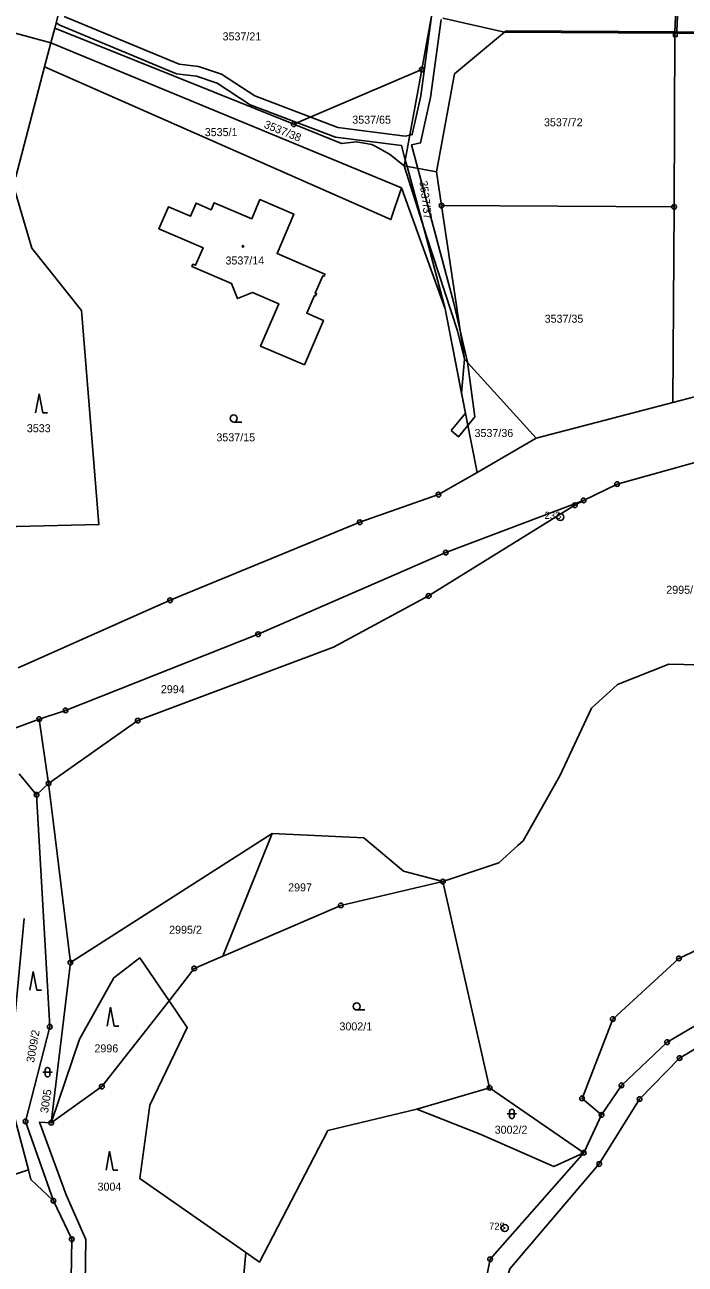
# Model space of a CAD drawing. Extents: x -644096 to -634268, y -1141430 to -1133463.
# Drawn here: x -641189.8 to -641049.4, y -1138498.2 to -1138235 of the extents above; entities that cross this region are included whole.
import ezdxf

# ---------------------------------------------------------------- set-up
doc = ezdxf.new("R2010")
doc.units = 0
for name, color, linetype in [('_CIVIL_CONSTRUCTION', 7, 'Continuous'), ('B_Hranice _3D', 7, 'Continuous'), ('M_Svah_Zarez', 7, 'Continuous'), ('svrsek_osa_sjezdy', 7, 'Continuous'), ('svrsek_osa_VRT', 7, 'Continuous'), ('terminal_VRT', 7, 'Continuous')]:
    doc.layers.add(name, color=color, linetype=linetype)

msp = doc.modelspace()

# ---------------------------------------------------------------- linework, layer by layer
at = {"layer": '_CIVIL_CONSTRUCTION'}
for centre, radius in [((-641105.4, -1138244.5), 0.5), ((-641105.4, -1138244.5), 0.0303), ((-641132.62, -1138256.11), 0.5), ((-641132.62, -1138256.11), 0.0303), ((-641101.19, -1138273.38), 0.5), ((-641101.19, -1138273.38), 0.0303), ((-641051.82, -1138273.67), 0.5), ((-641051.82, -1138273.67), 0.0303), ((-641063.91, -1138332.53), 0.5), ((-641063.91, -1138332.53), 0.0303), ((-641101.86, -1138334.78), 0.5), ((-641101.86, -1138334.78), 0.0303), ((-641071.03, -1138336.01), 0.5), ((-641072.89, -1138337.03), 0.5), ((-641072.89, -1138337.03), 0.0303), ((-641071.03, -1138336.01), 0.0303), ((-641118.59, -1138340.65), 0.5), ((-641118.59, -1138340.65), 0.0303), ((-641075.98, -1138339.54), 0.75), ((-641075.98, -1138339.54), 0.03), ((-641100.32, -1138347.08), 0.5), ((-641100.32, -1138347.08), 0.0303), ((-641103.95, -1138356.28), 0.5), ((-641103.95, -1138356.28), 0.0303), ((-641158.89, -1138357.22), 0.5), ((-641158.89, -1138357.22), 0.0303), ((-641140.18, -1138364.43), 0.5), ((-641140.18, -1138364.43), 0.0303), ((-641181.07, -1138380.59), 0.5), ((-641186.69, -1138382.45), 0.5), ((-641186.69, -1138382.45), 0.0303), ((-641181.07, -1138380.59), 0.0303), ((-641165.74, -1138382.77), 0.5), ((-641165.74, -1138382.77), 0.0303), ((-641184.69, -1138396.1), 0.5), ((-641184.69, -1138396.1), 0.0303), ((-641187.23, -1138398.51), 0.5), ((-641187.23, -1138398.51), 0.0303), ((-641100.92, -1138416.95), 0.5), ((-641100.92, -1138416.95), 0.0303), ((-641122.62, -1138422.02), 0.5), ((-641122.62, -1138422.02), 0.0303), ((-641050.79, -1138433.27), 0.5), ((-641180.05, -1138434.16), 0.5), ((-641180.05, -1138434.16), 0.0303), ((-641153.76, -1138435.4), 0.5), ((-641153.76, -1138435.4), 0.0303), ((-641050.79, -1138433.27), 0.0303), ((-641064.84, -1138446.16), 0.5), ((-641064.84, -1138446.16), 0.0303), ((-641184.44, -1138447.76), 0.5), ((-641184.44, -1138447.76), 0.0303), ((-641053.3, -1138451.05), 0.5), ((-641053.3, -1138451.05), 0.0303), ((-641050.64, -1138454.43), 0.5), ((-641050.64, -1138454.43), 0.0303), ((-641173.38, -1138460.49), 0.5), ((-641173.38, -1138460.49), 0.0303), ((-641091, -1138460.73), 0.5), ((-641091, -1138460.73), 0.0303), ((-641063, -1138460.22), 0.5), ((-641063, -1138460.22), 0.0303), ((-641071.35, -1138462.98), 0.5), ((-641071.35, -1138462.98), 0.0303), ((-641059.15, -1138463.14), 0.5), ((-641059.15, -1138463.14), 0.0303), ((-641067.21, -1138466.49), 0.5), ((-641067.21, -1138466.49), 0.0303), ((-641189.59, -1138467.89), 0.5), ((-641189.59, -1138467.89), 0.0303), ((-641184.12, -1138468.15), 0.5), ((-641184.12, -1138468.15), 0.0303), ((-641071.01, -1138474.54), 0.5), ((-641071.01, -1138474.54), 0.0303), ((-641067.71, -1138476.92), 0.5), ((-641067.71, -1138476.92), 0.0303), ((-641183.67, -1138484.72), 0.5), ((-641183.67, -1138484.72), 0.0303), ((-641087.78, -1138490.51), 0.75), ((-641087.78, -1138490.51), 0.03), ((-641179.76, -1138492.92), 0.5), ((-641179.76, -1138492.92), 0.0303), ((-641090.91, -1138497.15), 0.5), ((-641090.91, -1138497.15), 0.0303)]:
    msp.add_circle(centre, radius, dxfattribs=at)
at = {"layer": 'B_Hranice _3D'}
for points in [[(-641051.28, -1138228.2), (-641051.62, -1138236.49), (-641051.67, -1138236.81), (-641051.95, -1138236.82), (-641051.92, -1138237.49), (-641051.13, -1138237.48), (-641051.13, -1138236.8), (-641051.19, -1138236.27), (-641050.89, -1138228.19)], [(-641103.24, -1138232.67), (-641105.64, -1138250.05), (-641107.44, -1138258.31), (-641107.95, -1138258.42), (-641108.92, -1138258.63), (-641123.21, -1138256.78), (-641140.89, -1138250.11), (-641147.97, -1138245.46), (-641152.82, -1138243.82), (-641156.96, -1138243.33), (-641181.36, -1138233.21)], [(-641183.1, -1138234.61), (-641182.32, -1138235.09), (-641157.5, -1138245.38), (-641153.28, -1138245.88), (-641148.89, -1138247.36), (-641141.85, -1138251.99), (-641123.73, -1138258.84), (-641109.71, -1138260.64), (-641108.91, -1138263.64), (-641108.52, -1138265.08), (-641105.36, -1138276.86), (-641100.41, -1138295.3), (-641096.15, -1138317.44), (-641095.62, -1138320.1), (-641094.11, -1138318.27), (-641095.73, -1138306.64), (-641098.59, -1138294.14), (-641106.24, -1138265.5), (-641107.58, -1138260.49), (-641105.68, -1138260.09), (-641103.57, -1138250.41), (-641101.3, -1138233.85)], [(-641100.92, -1138233.57), (-641087.83, -1138236.59), (-641051.62, -1138236.79), (-641004.5, -1138237.04), (-640961.93, -1138237.27), (-640925.03, -1138237.47), (-640913.27, -1138237.4), (-640865, -1138233.88)]]:
    msp.add_lwpolyline(points, dxfattribs=at)
msp.add_lwpolyline([(-641099.2, -1138321.14), (-641097.58, -1138322.48), (-641095.62, -1138320.1), (-641096.15, -1138317.44)], close=True, dxfattribs=at)
at = {"layer": 'M_Svah_Zarez'}
msp.add_circle((-641143.39, -1138282.03), 0.175, dxfattribs=at)
at = {"layer": 'svrsek_osa_sjezdy'}
for p, q in [((-641186.7, -1138313.4), (-641187.45, -1138317.4)), ((-641185.95, -1138317.4), (-641186.7, -1138313.4)), ((-641185.95, -1138317.4), (-641184.95, -1138317.4)), ((-641145.36, -1138319.35), (-641143.61, -1138319.35)), ((-641187.94, -1138436.03), (-641188.69, -1138440.03)), ((-641187.19, -1138440.03), (-641187.94, -1138436.03)), ((-641187.19, -1138440.03), (-641186.19, -1138440.03)), ((-641171.51, -1138443.62), (-641172.26, -1138447.62)), ((-641170.76, -1138447.62), (-641171.51, -1138443.62)), ((-641119.23, -1138444.21), (-641117.48, -1138444.21)), ((-641170.76, -1138447.62), (-641169.76, -1138447.62)), ((-641185.92, -1138457.43), (-641183.92, -1138457.43)), ((-641185.42, -1138456.93), (-641185.42, -1138457.93)), ((-641184.42, -1138457.93), (-641184.42, -1138456.93)), ((-641087.26, -1138466.29), (-641085.26, -1138466.29)), ((-641086.76, -1138465.79), (-641086.76, -1138466.79)), ((-641085.76, -1138466.79), (-641085.76, -1138465.79)), ((-641171.72, -1138474.21), (-641172.47, -1138478.21)), ((-641170.97, -1138478.21), (-641171.72, -1138474.21)), ((-641170.97, -1138478.21), (-641169.97, -1138478.21))]:
    msp.add_line(p, q, dxfattribs=at)
for centre in [(-641145.36, -1138318.6), (-641119.23, -1138443.46)]:
    msp.add_circle(centre, 0.75, dxfattribs=at)
for centre, start, end in [((-641184.92, -1138456.93), 0, 180), ((-641184.92, -1138457.93), 180, 359.9879), ((-641086.26, -1138465.79), 0, 180), ((-641086.26, -1138466.79), 180, 359.9879)]:
    msp.add_arc(centre, 0.5, start, end, dxfattribs=at)
at = {"layer": 'terminal_VRT'}
for p, q in [((-641177.25, -1138212.28), (-641183.39, -1138235.71)), ((-641184.2, -1138238.82), (-641219.19, -1138229.34)), ((-641105.4, -1138244.5), (-641103.11, -1138231.97)), ((-641183.39, -1138235.71), (-641184.2, -1138238.82)), ((-641183.39, -1138235.71), (-641132.62, -1138256.11)), ((-641004.5, -1138236.74), (-641051.62, -1138236.49)), ((-641185.53, -1138243.91), (-641184.2, -1138238.82)), ((-641109.7, -1138269.6), (-641184.2, -1138238.82)), ((-641191.65, -1138267.26), (-641185.53, -1138243.91)), ((-641132.62, -1138256.11), (-641105.4, -1138244.5)), ((-641105.4, -1138244.5), (-641109.15, -1138264.97)), ((-641102.26, -1138266.23), (-641109.15, -1138264.97)), ((-641101.19, -1138273.38), (-641102.26, -1138266.23)), ((-641051.82, -1138273.67), (-641101.19, -1138273.38)), ((-641101.19, -1138273.38), (-641096.3, -1138306.01)), ((-641051.82, -1138273.67), (-641052.04, -1138315.2)), ((-641096.3, -1138306.01), (-641096.99, -1138313.23)), ((-641096.3, -1138306.01), (-641081.12, -1138322.81)), ((-641093.65, -1138330.04), (-641096.99, -1138313.23)), ((-641047.18, -1138313.93), (-641052.04, -1138315.2)), ((-641052.04, -1138315.2), (-641081.12, -1138322.81)), ((-641081.12, -1138322.81), (-641093.65, -1138330.04)), ((-641186.69, -1138382.45), (-641208.47, -1138390.55)), ((-641186.69, -1138382.45), (-641184.69, -1138396.1)), ((-641190.96, -1138394.04), (-641187.23, -1138398.51)), ((-641184.69, -1138396.1), (-641187.23, -1138398.51)), ((-641180.05, -1138434.16), (-641137.2, -1138406.72)), ((-641137.2, -1138406.72), (-641147.67, -1138432.78)), ((-641100.92, -1138416.95), (-641091, -1138460.73)), ((-641184.12, -1138468.15), (-641180.05, -1138434.16)), ((-641165.31, -1138433.17), (-641159.11, -1138442.24)), ((-641184.12, -1138468.15), (-641178.15, -1138450.41)), ((-641106.43, -1138465.31), (-641091, -1138460.73)), ((-641091, -1138460.73), (-641071.01, -1138474.54)), ((-641071.01, -1138474.54), (-641067.21, -1138466.49))]:
    msp.add_line(p, q, dxfattribs=at)
for points in [[(-641102.26, -1138266.23), (-641098.45, -1138245.39), (-641087.83, -1138236.59), (-641087.47, -1138236.29), (-641051.62, -1138236.49)], [(-641051.62, -1138236.49), (-641051.62, -1138236.79), (-641051.82, -1138273.67)], [(-641185.53, -1138243.91), (-641111.97, -1138276.35), (-641109.7, -1138269.6)], [(-641109.15, -1138264.97), (-641112.26, -1138262.48), (-641115.3, -1138260.8), (-641115.99, -1138260.39), (-641119.26, -1138259.84), (-641122.47, -1138260.19), (-641132.62, -1138256.11)], [(-641109.15, -1138264.97), (-641104.39, -1138279.89), (-641097.82, -1138299.99), (-641096.3, -1138306.01)], [(-641196.58, -1138347.41), (-641191.59, -1138341.56), (-641173.99, -1138341.13), (-641177.7, -1138295.65), (-641188.26, -1138282.45), (-641192.16, -1138269.19)], [(-641096.99, -1138313.23), (-641100.41, -1138295.3), (-641109.7, -1138269.6)], [(-641130.33, -1138307.23), (-641126.29, -1138297.76), (-641129.86, -1138296.22), (-641128.23, -1138292.47), (-641127.96, -1138292.58), (-641127.76, -1138292.11), (-641128.04, -1138291.99), (-641126.44, -1138288.28), (-641126.17, -1138288.39), (-641125.97, -1138287.92), (-641136.15, -1138283.56), (-641132.59, -1138275.22), (-641139.8, -1138272.11), (-641141.54, -1138276.2), (-641149.52, -1138272.79), (-641150.14, -1138274.27), (-641153.35, -1138272.87), (-641154.53, -1138275.65), (-641159.22, -1138273.63), (-641161.24, -1138278.32), (-641151.86, -1138282.33), (-641153.48, -1138286.07), (-641154.02, -1138285.84), (-641154.23, -1138286.32), (-641145.84, -1138289.92), (-641144.58, -1138293.13), (-641141.35, -1138291.84), (-641135.78, -1138294.23), (-641139.66, -1138303.27), (-641130.33, -1138307.23)], [(-640920.03, -1138300.09), (-640958.49, -1138308.44), (-640997.07, -1138316.04), (-641037.47, -1138325.22), (-641063.91, -1138332.53), (-641071.03, -1138336.01)], [(-641093.65, -1138330.04), (-641101.86, -1138334.78), (-641118.59, -1138340.65), (-641158.89, -1138357.22), (-641191.13, -1138371.53)], [(-641071.03, -1138336.01), (-641100.32, -1138347.08), (-641140.18, -1138364.43), (-641181.07, -1138380.59), (-641186.69, -1138382.45)], [(-641184.69, -1138396.1), (-641165.74, -1138382.77), (-641124.17, -1138367.15), (-641103.95, -1138356.28), (-641072.89, -1138337.03), (-641071.03, -1138336.01)], [(-641100.92, -1138416.95), (-641089.06, -1138412.97), (-641085.03, -1138409.27), (-641083.86, -1138408.27), (-641076.09, -1138394.5), (-641069.37, -1138380.11), (-641063.81, -1138375.12), (-641052.9, -1138370.75), (-641036.94, -1138371.12), (-641030.53, -1138369.62), (-641023.92, -1138364.96), (-641018.21, -1138352.84), (-641012.65, -1138345.79), (-641003.67, -1138340.21), (-640990.54, -1138338.79), (-640982.43, -1138341.99), (-640963.06, -1138356.09), (-640958.13, -1138354.94), (-640910.39, -1138342.99)], [(-641184.69, -1138396.1), (-641183.72, -1138404.04), (-641180.05, -1138434.16)], [(-641187.23, -1138398.51), (-641184.44, -1138447.76), (-641189.59, -1138467.89), (-641183.67, -1138484.72)], [(-641137.2, -1138406.72), (-641117.73, -1138407.66), (-641109.28, -1138414.74), (-641100.92, -1138416.95)], [(-640960.2, -1138410.8), (-641018.57, -1138435.41), (-641050.64, -1138454.43), (-641059.15, -1138463.14), (-641067.71, -1138476.92), (-641086.73, -1138499.16), (-641089.16, -1138507.92), (-641081.75, -1138551.74), (-641080.18, -1138564.7), (-641080.51, -1138574.35), (-641087.13, -1138586.78), (-641095.84, -1138597.28), (-641129.98, -1138625.16)], [(-641067.21, -1138466.49), (-641071.35, -1138462.98), (-641064.84, -1138446.16), (-641050.79, -1138433.27), (-641033.02, -1138424.89), (-640985.84, -1138413.83)], [(-641147.67, -1138432.78), (-641146.97, -1138432.48), (-641122.62, -1138422.02), (-641100.92, -1138416.95)], [(-641067.21, -1138466.49), (-641063, -1138460.22), (-641053.3, -1138451.05), (-641020.54, -1138431.85), (-640980.59, -1138415.22)], [(-641189.88, -1138424.76), (-641191.7, -1138444.4), (-641193.87, -1138458.01), (-641193.62, -1138460.56), (-641188.97, -1138478.19)], [(-641147.67, -1138432.78), (-641153.76, -1138435.4), (-641159.11, -1138442.24)], [(-641178.15, -1138450.41), (-641170.84, -1138437.38), (-641165.31, -1138433.17)], [(-641159.11, -1138442.24), (-641173.38, -1138460.49), (-641184.12, -1138468.15)], [(-641159.11, -1138442.24), (-641155.23, -1138447.92), (-641163.18, -1138464.43), (-641165.3, -1138480.01), (-641158.74, -1138484.59), (-641143.99, -1138494.89), (-641142.76, -1138495.75)], [(-641142.76, -1138495.75), (-641139.89, -1138497.75), (-641125.36, -1138469.78), (-641106.43, -1138465.31)], [(-641106.43, -1138465.31), (-641092.99, -1138470.59), (-641077.34, -1138477.47), (-641071.01, -1138474.54)], [(-641184.12, -1138468.15), (-641186.62, -1138468.03), (-641180.99, -1138483.44), (-641176.75, -1138492.97), (-641176.97, -1138506.91), (-641178.94, -1138517.13)], [(-641071.01, -1138474.54), (-641090.91, -1138497.15), (-641093, -1138507.82), (-641085.45, -1138552.15), (-641083.98, -1138564.03), (-641085.51, -1138573.59), (-641089.6, -1138584.36), (-641098.16, -1138594.44), (-641125.32, -1138616.68)], [(-641188.97, -1138478.19), (-641233.23, -1138492.66), (-641238.54, -1138478.95), (-641243.06, -1138480.56)], [(-641183.67, -1138484.72), (-641188.44, -1138480.2), (-641188.97, -1138478.19)], [(-641183.67, -1138484.72), (-641179.76, -1138492.92), (-641179.89, -1138501.24)], [(-641150.57, -1138531.97), (-641144.18, -1138511.35), (-641142.76, -1138495.75)]]:
    msp.add_lwpolyline(points, dxfattribs=at)

# ---------------------------------------------------------------- texts
at = {"layer": '_CIVIL_CONSTRUCTION'}
for s, p in [('232', (-641079.32, -1138339.92)), ('728', (-641091.12, -1138490.89))]:
    msp.add_text(s, height=1.5, dxfattribs=at).set_placement(p)
at = {"layer": 'svrsek_osa_VRT'}
for s, p in [('3537/21', (-641147.73, -1138238.31)), ('3537/65', (-641120.18, -1138256)), ('3537/72', (-641079.45, -1138256.55)), ('3535/1', (-641151.52, -1138258.64)), ('3537/14', (-641147.11, -1138285.9)), ('3537/35', (-641079.31, -1138298.27)), ('3533', (-641189.31, -1138321.52)), ('3537/15', (-641149.04, -1138323.45)), ('3537/36', (-641094.2, -1138322.53)), ('2995/1', (-641053.47, -1138355.83)), ('2994', (-641160.84, -1138376.94)), ('2997', (-641133.8, -1138419.03)), ('2995/2', (-641159.08, -1138428.02)), ('3002/1', (-641122.9, -1138448.55)), ('2996', (-641174.95, -1138453.22)), ('3002/2', (-641089.92, -1138470.49)), ('3004', (-641174.29, -1138482.58))]:
    msp.add_text(s, height=1.7, dxfattribs=at).set_placement(p)
for s, rotation, p in [('3537/38', 338, (-641139.08, -1138256.79)), ('3537/37', 277, (-641105.9, -1138268.21)), ('3009/2', 80, (-641187.78, -1138455.47)), ('3005', 81, (-641184.83, -1138466.19))]:
    msp.add_text(s, height=1.7, rotation=rotation, dxfattribs=at).set_placement(p)

doc.saveas('drawing.dxf')
